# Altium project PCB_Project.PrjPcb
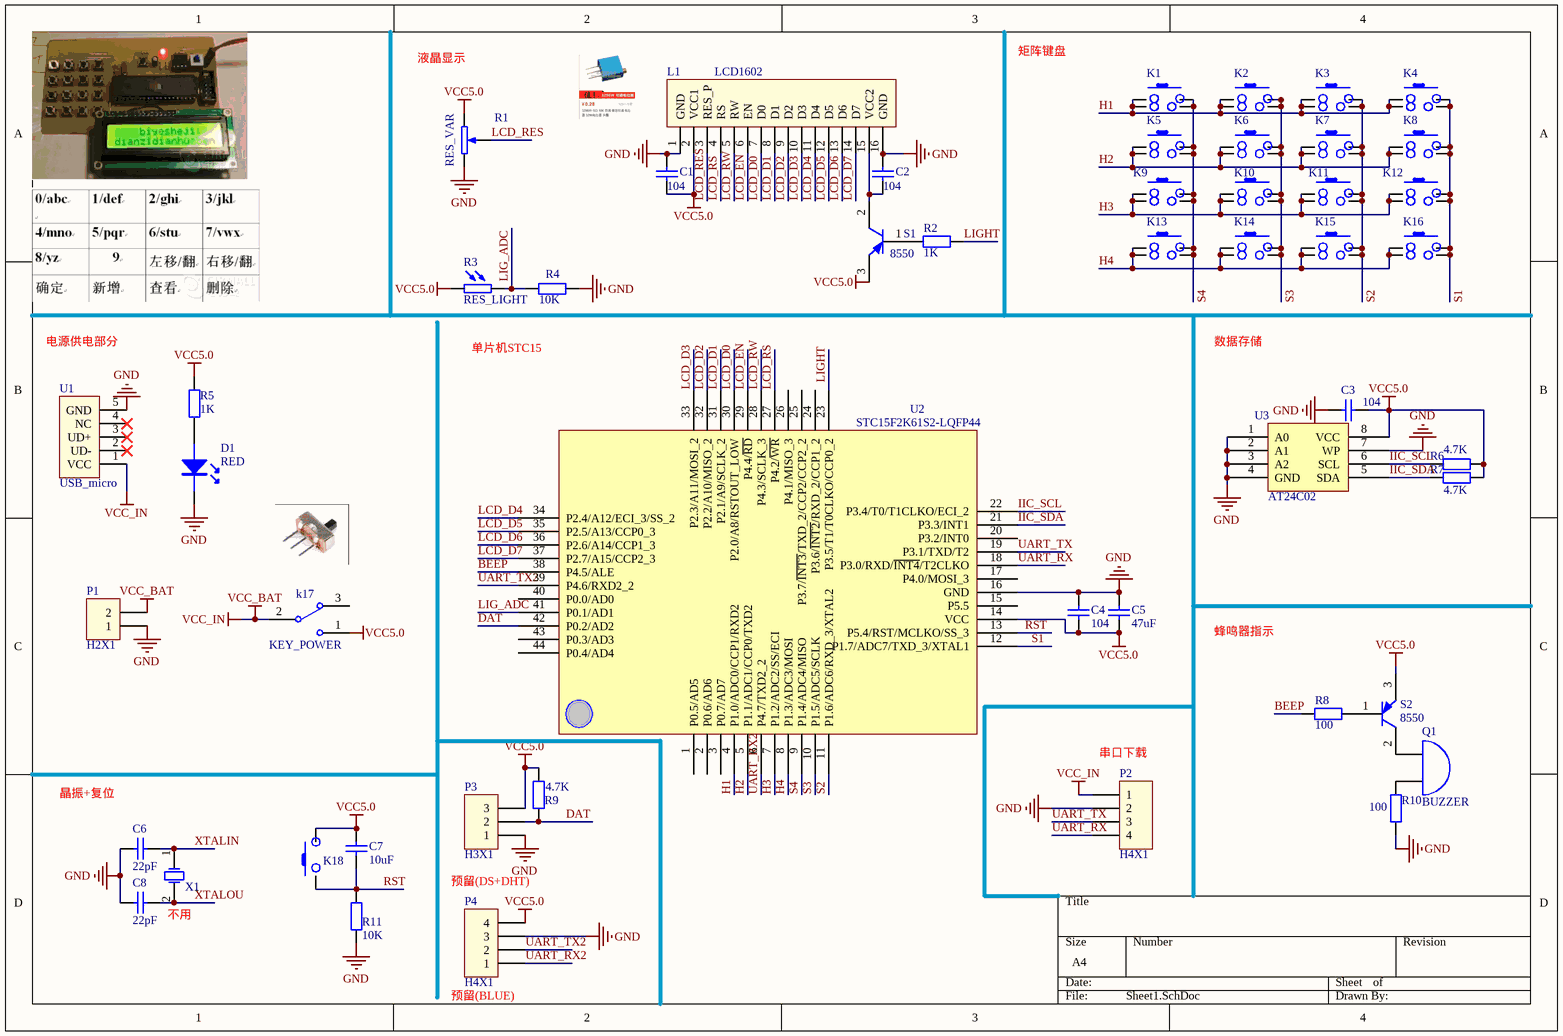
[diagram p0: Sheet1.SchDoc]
1 sheet, 50 parts. Net scope: global (net labels, ports and power ports of the same name join across sheets).
Board file: PCB1.PcbDoc

## Sheet Sheet1.SchDoc
size A4

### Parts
C1  104  [RLC_0603]
C2  104  [RLC_0603]
C3  104  [RLC_0603]
C4  104  [RLC_0603]
C5  value 47uF  [RLC_0603]  (hidden comment: 104)
C6  value 22pF  [RLC_0603]  (hidden comment: 104)
C7  value 10uF  [RLC_0603]  (hidden comment: 104)
C8  value 22pF  [RLC_0603]  (hidden comment: 104)
D1  RED  [LED_0603]
K1  KEY_4(SMD)  [key4(dip)]  (value not drawn)
K2  KEY_4(SMD)  [key4(dip)]  (value not drawn)
K3  KEY_4(SMD)  [key4(dip)]  (value not drawn)
K4  KEY_4(SMD)  [key4(dip)]  (value not drawn)
K5  KEY_4(SMD)  [key4(dip)]  (value not drawn)
K6  KEY_4(SMD)  [key4(dip)]  (value not drawn)
K7  KEY_4(SMD)  [key4(dip)]  (value not drawn)
K8  KEY_4(SMD)  [key4(dip)]  (value not drawn)
K9  KEY_4(SMD)  [key4(dip)]  (value not drawn)
K10  KEY_4(SMD)  [key4(dip)]  (value not drawn)
K11  KEY_4(SMD)  [key4(dip)]  (value not drawn)
K12  KEY_4(SMD)  [key4(dip)]  (value not drawn)
K13  KEY_4(SMD)  [key4(dip)]  (value not drawn)
K14  KEY_4(SMD)  [key4(dip)]  (value not drawn)
K15  KEY_4(SMD)  [key4(dip)]  (value not drawn)
K16  KEY_4(SMD)  [key4(dip)]  (value not drawn)
k17  KEY_POWER  [SW_POWER_KEY]
K18  KEY_BIG  [KEY_2(SMD)]  (value not drawn)
L1  LCD1602  [LCD1602]
P1  H2X1  [H2.54-1X2]
P2  H4X1  [H2.54-1X4]
P3  H3X1  [H2.54-1X3]
P4  H4X1  [H2.54-1X4]
Q1  BUZZER  [Buzzer_9*5.5mm]
R1  RES_VAR  [RES_VAR]
R2  value 1K  [RLC_0603]  (hidden comment: 510R)
R3  RES_LIGHT  [H2.54-1X2]
R4  value 10K  [RLC_0603]  (hidden comment: 510R)
R5  value 1K  [RLC_0603]  (hidden comment: 510R)
R6  value 4.7K  [RLC_0603]  (hidden comment: 510R)
R7  value 4.7K  [RLC_0603]  (hidden comment: 510R)
R8  value 100  [RLC_0603]  (hidden comment: 510R)
R9  value 4.7K  [RLC_0603]  (hidden comment: 510R)
R10  value 100  [RLC_0603]  (hidden comment: 510R)
R11  value 10K  [RLC_0603]  (hidden comment: 510R)
S1  8550  [SOT23A]
S2  8550  [SOT23A]
U1  USB_micro  [USB(micro)]
U2  STC15F2K61S2-LQFP44  [MCU_LQFP44]
U3  AT24C02  [SO-8]
X1  XTAL_2DIP  [XTAL_2DIP]  (value not drawn)

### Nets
GND: C1.2 C2.2 C3.1 C4.1 C5.1 C6.1 C8.1 D1.2 L1.1(GND) L1.16(GND) P1.1 P2.2 P3.1 P4.3 R1.3 R4.2 R10.2 R11.1 U1.5(GND) U2.16(GND) U3.1(A0) U3.2(A1) U3.3(A2) U3.4(GND) U3.7(WP)
VCC5.0: C1.1 C3.2 C4.2 C5.2 C7.2 k17.1 K18.2 L1.2(VCC1) P3.3 P4.4 R1.1 R3.1 R5.1 R6.1 R7.1 R9.2 S1.3(C) S2.3(C) U2.14(VCC) U3.8(VCC)
VCC_BAT: k17.2 P1.2 P2.1 U1.1(VCC)  [also labelled VCC_IN]
BEEP: R8.2 U2.38(P4.5/ALE)
DAT: P3.2 R9.1 U2.42(P0.2/AD2)
H1: K1.1 K1.2 K2.1 K2.2 K3.1 K3.2 K4.1 K4.2 U2.4(P1.0/ADC0/CCP1/RXD2)
H2: K5.1 K5.2 K6.1 K6.2 K7.1 K7.2 K8.1 K8.2 U2.5(P1.1/ADC1/CCP0/TXD2)
H3: K9.1 K9.2 K10.1 K10.2 K11.1 K11.2 K12.1 K12.2 U2.7(P1.2/ADC2/SS/ECI)
H4: K13.1 K13.2 K14.1 K14.2 K15.1 K15.2 K16.1 K16.2 U2.8(P1.3/ADC3/MOSI)
IIC_SCL: R6.2 U2.22(P3.4/T0/T1CLKO/ECI_2) U3.6(SCL)
IIC_SDA: R7.2 U2.21(P3.3/INT1) U3.5(SDA)
LCD_D0: L1.7(D0) U2.30(P2.0/A8/RSTOUT_LOW)
LCD_D1: L1.8(D1) U2.31(P2.1/A9/SCLK_2)
LCD_D2: L1.9(D2) U2.32(P2.2/A10/MISO_2)
LCD_D3: L1.10(D3) U2.33(P2.3/A11/MOSI_2)
LCD_D4: L1.11(D4) U2.34(P2.4/A12/ECI_3/SS_2)
LCD_D5: L1.12(D5) U2.35(P2.5/A13/CCP0_3)
LCD_D6: L1.13(D6) U2.36(P2.6/A14/CCP1_3)
LCD_D7: L1.14(D7) U2.37(P2.7/A15/CCP2_3)
LCD_EN: L1.6(EN) U2.29(P4.4/~{RD})
LCD_RES: L1.3(RES_P) R1.2
LCD_RS: L1.4(RS) U2.27(P4.2/~{WR})
LCD_RW: L1.5(RW) U2.28(P4.3/SCLK_3)
LIG_ADC: R3.2 R4.1 U2.41(P0.1/AD1)
LIGHT: R2.2 U2.23(P3.5/T1/T0CLKO/CCP0_2)
RST: C7.1 K18.1 R11.2 U2.13(P5.4/RST/MCLKO/SS_3)
S1: K4.3 K4.4 K8.3 K8.4 K12.3 K12.4 K16.3 K16.4 U2.12(P1.7/ADC7/TXD_3/XTAL1)
S2: K3.3 K3.4 K7.3 K7.4 K11.3 K11.4 K15.3 K15.4 U2.11(P1.6/ADC6/RXD_3/XTAL2)
S3: K2.3 K2.4 K6.3 K6.4 K10.3 K10.4 K14.3 K14.4 U2.10(P1.5/ADC5/SCLK)
S4: K1.3 K1.4 K5.3 K5.4 K9.3 K9.4 K13.3 K13.4 U2.9(P1.4/ADC4/MISO)
UART_RX: P2.4 U2.18(P3.0/RXD/~{INT4}/T2CLKO)
UART_RX2: P4.1 U2.6(P4.7/TXD2_2)
UART_TX: P2.3 U2.19(P3.1/TXD/T2)
UART_TX2: P4.2 U2.39(P4.6/RXD2_2)
XTALIN: C6.2 X1.1(OSC1)
XTALOU: C8.2 X1.2(OSC2)
NetC2_1: C2.1 L1.15(VCC2) S1.2(E)
NetD1_1: D1.1 R5.2
NetQ1_1: Q1.1(A) S2.2(E)
NetQ1_2: Q1.2(B) R10.1
NetR2_1: R2.1 S1.1(B)
NetR8_1: R8.1 S2.1(B)

Not connected (* = marked no-connect by the designer): k17 3; U1 2(UD-)* 3(UD+)* 4(NC)*; U2 1(P0.5/AD5) 2(P0.6/AD6) 3(P0.7/AD7) 15(P5.5) 17(P4.0/MOSI_3) 20(P3.2/INT0) 24(P3.6/~{INT2}/RXD_2/CCP1_2) 25(P3.7/~{INT3}/TXD_2/CCP2/CCP2_2) 26(P4.1/MISO_3) 40(P0.0/AD0) 43(P0.3/AD3) 44(P0.4/AD4)

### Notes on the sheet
- 液晶显示
- 矩阵键盘
- 电源供电部分
- 单片机STC15
- 数据存储
- 蜂鸣器指示
- (near P2) 串口下载
- 晶振+复位
- 不用
- 预留(DS+DHT)
- (near P4) 预留(BLUE)

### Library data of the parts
C1-C8 = Cap: Capacitor
D1 = LED
R2 R4-R11 = Res2: Resistor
